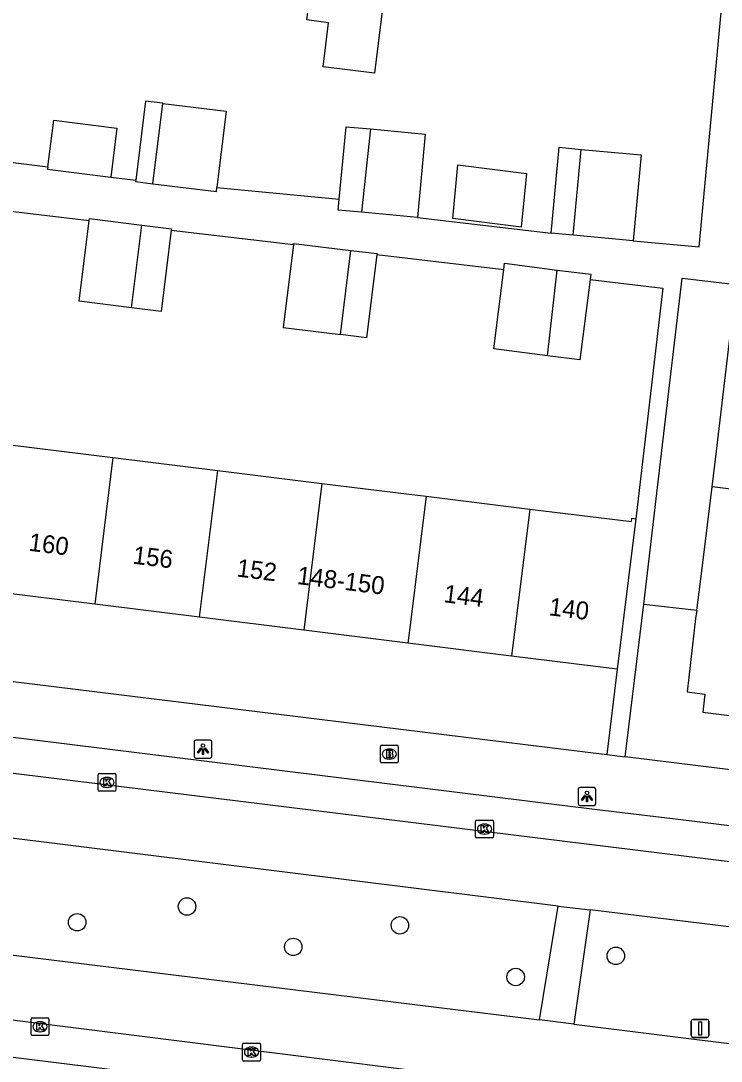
# Model space of a CAD drawing. Extents: x 158087 to 159494, y 382905 to 383981.
# Drawn here: x 158478.3 to 158517.5, y 383380.9 to 383439.1 of the extents above; entities that cross this region are included whole.
import ezdxf

# ---------------------------------------------------------------- set-up
doc = ezdxf.new("R2010")
doc.units = 0
for name, color, linetype in [('IMGEO_Boom', 7, 'Continuous'), ('IMGEO_Brandkraan', 7, 'Continuous'), ('IMGEO_Kolk', 7, 'Continuous'), ('IMGEO_Lichtpunt', 7, 'Continuous'), ('IMGEO_Pand', 7, 'Continuous'), ('IMGEO_Pand_nummerreeks', 7, 'Continuous'), ('IMGEO_Rijbaan_lokaal_gesloten', 7, 'Continuous'), ('IMGEO_Verkeersbordpaal', 7, 'Continuous'), ('IMGEO_Voetpad_open', 7, 'Continuous')]:
    doc.layers.add(name, color=color, linetype=linetype)

msp = doc.modelspace()

# ---------------------------------------------------------------- linework, layer by layer
at = {"layer": 'IMGEO_Boom'}
for centre in [(158487.569, 383389.572), (158481.416, 383388.692), (158499.487, 383388.521), (158493.514, 383387.313), (158511.575, 383386.812), (158505.97, 383385.631)]:
    msp.add_circle(centre, 0.489, dxfattribs=at)
at = {"layer": 'IMGEO_Brandkraan'}
for p, q in [((158498.397, 383397.676), (158498.397, 383398.528)), ((158498.472, 383398.602), (158499.324, 383398.602)), ((158498.885, 383398.382), (158498.91, 383398.382)), ((158499.398, 383398.528), (158499.398, 383397.676)), ((158498.908, 383397.822), (158498.883, 383397.822)), ((158499.324, 383397.602), (158498.472, 383397.602))]:
    msp.add_line(p, q, dxfattribs=at)
for points in [[(158498.397, 383397.676), (158498.397, 383398.528)], [(158498.472, 383398.602), (158499.324, 383398.602)], [(158499.398, 383398.528), (158499.398, 383397.676)], [(158498.745, 383398.302), (158498.745, 383397.902), (158498.958, 383397.902)], [(158498.976, 383398.302), (158498.745, 383398.302)], [(158498.924, 383398.221), (158498.87, 383398.221), (158498.87, 383398.145)], [(158498.87, 383398.145), (158498.923, 383398.145)], [(158498.932, 383398.069), (158498.87, 383398.069), (158498.87, 383397.988)], [(158498.87, 383397.988), (158498.932, 383397.988)], [(158499.324, 383397.602), (158498.472, 383397.602)]]:
    msp.add_lwpolyline(points, dxfattribs=at)
for centre, radius, start, end in [((158498.474, 383398.526), 0.0765, 91.55205, 178.44795), ((158498.474, 383398.526), 0.0765, 91.55205, 178.44795), ((158499.322, 383398.526), 0.0765, 1.55205, 88.44795), ((158499.322, 383398.526), 0.0765, 1.55205, 88.44795), ((158498.925, 383398.183), 0.0379, 267.82845, 90.93552), ((158498.933, 383398.028), 0.0404, 269.87594, 90.50774), ((158498.964, 383398.153), 0.251, 268.66757, 293.53466), ((158498.98, 383398.157), 0.145, 59.4692, 91.53667), ((158499.005, 383398.204), 0.0922, 285.51372, 58.15012), ((158499.01, 383398.012), 0.105, 301.31148, 78.98903), ((158498.474, 383397.678), 0.0765, 181.55205, 268.44795), ((158498.474, 383397.678), 0.0765, 181.55205, 268.44795), ((158499.322, 383397.678), 0.0765, 271.55205, 358.44795), ((158499.322, 383397.678), 0.0765, 271.55205, 358.44795)]:
    msp.add_arc(centre, radius, start, end, dxfattribs=at)
for centre, major_axis, ratio, start_param, end_param in [((158498.884, 383398.102), (-0.387, 0.002), 0.722429, 4.712389, 7.853982), ((158498.909, 383398.102), (-0.39, 0.002), 0.717154, 1.570796, 4.712389)]:
    msp.add_ellipse(centre, major_axis=major_axis, ratio=ratio, start_param=start_param, end_param=end_param, dxfattribs=at)
at = {"layer": 'IMGEO_Kolk'}
for p, q in [((158482.586, 383396.091), (158482.586, 383396.943)), ((158482.661, 383397.017), (158483.513, 383397.017)), ((158483.074, 383396.797), (158483.099, 383396.797)), ((158483.587, 383396.943), (158483.587, 383396.091)), ((158483.513, 383396.017), (158482.661, 383396.017)), ((158483.097, 383396.237), (158483.072, 383396.237)), ((158503.724, 383393.481), (158503.724, 383394.333)), ((158503.799, 383394.407), (158504.651, 383394.407)), ((158504.725, 383394.333), (158504.725, 383393.481)), ((158504.212, 383394.187), (158504.237, 383394.187)), ((158504.651, 383393.407), (158503.799, 383393.407)), ((158504.235, 383393.627), (158504.21, 383393.627)), ((158478.835, 383382.423), (158478.835, 383383.275)), ((158478.91, 383383.349), (158479.762, 383383.349)), ((158479.836, 383383.275), (158479.836, 383382.423)), ((158479.323, 383383.129), (158479.348, 383383.129)), ((158479.762, 383382.349), (158478.91, 383382.349)), ((158479.346, 383382.569), (158479.321, 383382.569)), ((158490.677, 383381.003), (158490.677, 383381.855)), ((158490.752, 383381.929), (158491.604, 383381.929)), ((158491.165, 383381.709), (158491.19, 383381.709)), ((158491.678, 383381.855), (158491.678, 383381.003)), ((158491.604, 383380.929), (158490.752, 383380.929)), ((158491.188, 383381.149), (158491.163, 383381.149))]:
    msp.add_line(p, q, dxfattribs=at)
for points in [[(158482.586, 383396.091), (158482.586, 383396.943)], [(158482.661, 383397.017), (158483.513, 383397.017)], [(158482.907, 383396.717), (158483.03, 383396.717), (158483.03, 383396.566), (158483.16, 383396.717), (158483.324, 383396.717), (158483.178, 383396.566), (158483.331, 383396.317), (158483.179, 383396.317), (158483.094, 383396.481), (158483.03, 383396.414), (158483.03, 383396.317), (158482.907, 383396.317), (158482.907, 383396.717)], [(158483.587, 383396.943), (158483.587, 383396.091)], [(158483.513, 383396.017), (158482.661, 383396.017)], [(158503.724, 383393.481), (158503.724, 383394.333)], [(158503.799, 383394.407), (158504.651, 383394.407)], [(158504.725, 383394.333), (158504.725, 383393.481)], [(158504.045, 383394.107), (158504.168, 383394.107), (158504.168, 383393.956), (158504.298, 383394.107), (158504.462, 383394.107), (158504.316, 383393.956), (158504.469, 383393.707), (158504.317, 383393.707), (158504.232, 383393.871), (158504.168, 383393.804), (158504.168, 383393.707), (158504.045, 383393.707), (158504.045, 383394.107)], [(158504.651, 383393.407), (158503.799, 383393.407)], [(158478.835, 383382.423), (158478.835, 383383.275)], [(158478.91, 383383.349), (158479.762, 383383.349)], [(158479.836, 383383.275), (158479.836, 383382.423)], [(158479.156, 383383.049), (158479.279, 383383.049), (158479.279, 383382.898), (158479.409, 383383.049), (158479.573, 383383.049), (158479.427, 383382.898), (158479.58, 383382.649), (158479.428, 383382.649), (158479.343, 383382.813), (158479.279, 383382.746), (158479.279, 383382.649), (158479.156, 383382.649), (158479.156, 383383.049)], [(158479.762, 383382.349), (158478.91, 383382.349)], [(158490.677, 383381.003), (158490.677, 383381.855)], [(158490.752, 383381.929), (158491.604, 383381.929)], [(158490.998, 383381.629), (158491.121, 383381.629), (158491.121, 383381.478), (158491.251, 383381.629), (158491.415, 383381.629), (158491.269, 383381.478), (158491.422, 383381.229), (158491.27, 383381.229), (158491.185, 383381.393), (158491.121, 383381.326), (158491.121, 383381.229), (158490.998, 383381.229), (158490.998, 383381.629)], [(158491.678, 383381.855), (158491.678, 383381.003)], [(158491.604, 383380.929), (158490.752, 383380.929)]]:
    msp.add_lwpolyline(points, dxfattribs=at)
for centre, start, end in [((158482.663, 383396.941), 91.55205, 178.44795), ((158482.663, 383396.941), 91.55205, 178.44795), ((158483.511, 383396.941), 1.55205, 88.44795), ((158483.511, 383396.941), 1.55205, 88.44795), ((158482.663, 383396.093), 181.55205, 268.44795), ((158482.663, 383396.093), 181.55205, 268.44795), ((158483.511, 383396.093), 271.55205, 358.44795), ((158483.511, 383396.093), 271.55205, 358.44795), ((158503.801, 383394.331), 91.55205, 178.44795), ((158503.801, 383394.331), 91.55205, 178.44795), ((158504.649, 383394.331), 1.55205, 88.44795), ((158504.649, 383394.331), 1.55205, 88.44795), ((158503.801, 383393.483), 181.55205, 268.44795), ((158503.801, 383393.483), 181.55205, 268.44795), ((158504.649, 383393.483), 271.55205, 358.44795), ((158504.649, 383393.483), 271.55205, 358.44795), ((158478.912, 383383.273), 91.55205, 178.44795), ((158478.912, 383383.273), 91.55205, 178.44795), ((158479.76, 383383.273), 1.55205, 88.44795), ((158479.76, 383383.273), 1.55205, 88.44795), ((158478.912, 383382.425), 181.55205, 268.44795), ((158478.912, 383382.425), 181.55205, 268.44795), ((158479.76, 383382.425), 271.55205, 358.44795), ((158479.76, 383382.425), 271.55205, 358.44795), ((158490.754, 383381.853), 91.55205, 178.44795), ((158490.754, 383381.853), 91.55205, 178.44795), ((158491.602, 383381.853), 1.55205, 88.44795), ((158491.602, 383381.853), 1.55205, 88.44795), ((158490.754, 383381.005), 181.55205, 268.44795), ((158490.754, 383381.005), 181.55205, 268.44795), ((158491.602, 383381.005), 271.55205, 358.44795), ((158491.602, 383381.005), 271.55205, 358.44795)]:
    msp.add_arc(centre, 0.0765, start, end, dxfattribs=at)
for centre, major_axis, ratio, start_param, end_param in [((158483.073, 383396.517), (-0.387, 0.002), 0.722429, 4.712389, 7.853982), ((158483.098, 383396.517), (-0.39, 0.002), 0.717154, 1.570796, 4.712389), ((158504.211, 383393.907), (-0.387, 0.002), 0.722429, 4.712389, 7.853982), ((158504.236, 383393.907), (-0.39, 0.002), 0.717154, 1.570796, 4.712389), ((158479.322, 383382.849), (-0.387, 0.002), 0.722429, 4.712389, 7.853982), ((158479.347, 383382.849), (-0.39, 0.002), 0.717154, 1.570796, 4.712389), ((158491.164, 383381.429), (-0.387, 0.002), 0.722429, 4.712389, 7.853982), ((158491.189, 383381.429), (-0.39, 0.002), 0.717154, 1.570796, 4.712389)]:
    msp.add_ellipse(centre, major_axis=major_axis, ratio=ratio, start_param=start_param, end_param=end_param, dxfattribs=at)
at = {"layer": 'IMGEO_Lichtpunt'}
for p, q in [((158487.963, 383398.781), (158487.963, 383397.974)), ((158487.963, 383398.781), (158487.963, 383397.974)), ((158488.865, 383398.876), (158488.057, 383398.876)), ((158488.865, 383398.876), (158488.057, 383398.876)), ((158488.959, 383397.974), (158488.959, 383398.781)), ((158488.959, 383397.974), (158488.959, 383398.781)), ((158488.057, 383397.88), (158488.865, 383397.88)), ((158488.057, 383397.88), (158488.865, 383397.88)), ((158509.46, 383396.131), (158509.46, 383395.324)), ((158509.46, 383396.131), (158509.46, 383395.324)), ((158510.362, 383396.226), (158509.554, 383396.226)), ((158510.362, 383396.226), (158509.554, 383396.226)), ((158510.456, 383395.324), (158510.456, 383396.131)), ((158510.456, 383395.324), (158510.456, 383396.131)), ((158509.554, 383395.23), (158510.362, 383395.23)), ((158509.554, 383395.23), (158510.362, 383395.23))]:
    msp.add_line(p, q, dxfattribs=at)
for points in [[(158488.337, 383398.445), (158488.376, 383398.417), (158488.188, 383398.155), (158488.15, 383398.182), (158488.337, 383398.445)], [(158488.439, 383398.397), (158488.486, 383398.397), (158488.486, 383398.075), (158488.439, 383398.075), (158488.439, 383398.397)], [(158488.549, 383398.417), (158488.587, 383398.444), (158488.774, 383398.182), (158488.735, 383398.154), (158488.549, 383398.417)], [(158509.834, 383395.795), (158509.873, 383395.767), (158509.685, 383395.505), (158509.647, 383395.532), (158509.834, 383395.795)], [(158509.936, 383395.747), (158509.983, 383395.747), (158509.983, 383395.425), (158509.936, 383395.425), (158509.936, 383395.747)], [(158510.046, 383395.767), (158510.084, 383395.794), (158510.271, 383395.532), (158510.232, 383395.504), (158510.046, 383395.767)]]:
    msp.add_lwpolyline(points, dxfattribs=at)
for centre in [(158488.462, 383398.579), (158509.959, 383395.929)]:
    msp.add_circle(centre, 0.0994, dxfattribs=at)
for centre, start, end in [((158488.057, 383398.781), 90, 180), ((158488.057, 383398.781), 90, 180), ((158488.865, 383398.781), 0, 90), ((158488.865, 383398.781), 0, 90), ((158488.057, 383397.974), 180, 270), ((158488.057, 383397.974), 180, 270), ((158488.865, 383397.974), 270, 0), ((158488.865, 383397.974), 270, 360), ((158509.554, 383396.131), 90, 180), ((158509.554, 383396.131), 90, 180), ((158510.362, 383396.131), 0, 90), ((158510.362, 383396.131), 0, 90), ((158509.554, 383395.324), 180, 270), ((158509.554, 383395.324), 180, 270), ((158510.362, 383395.324), 270, 0), ((158510.362, 383395.324), 270, 360)]:
    msp.add_arc(centre, 0.0946, start, end, dxfattribs=at)
at = {"layer": 'IMGEO_Pand'}
for points in [[(158499.119, 383444.667), (158498.064, 383436.195), (158495.188, 383436.554), (158495.495, 383439.018), (158494.273, 383439.17), (158494.738, 383442.903), (158496.734, 383442.655), (158497.017, 383444.928), (158493.033, 383445.425)], [(158486.219, 383434.5), (158486.22, 383434.509), (158485.248, 383434.63), (158484.696, 383430.206)], [(158485.659, 383430.01), (158486.219, 383434.5)], [(158486.219, 383434.5), (158489.768, 383434.063), (158489.243, 383429.791)], [(158479.78, 383430.955), (158480.105, 383433.56), (158483.634, 383433.12), (158483.293, 383430.381)], [(158496.092, 383429.148), (158496.472, 383433.2), (158497.843, 383433.072)], [(158497.843, 383433.072), (158497.33, 383428.41)], [(158497.843, 383433.072), (158500.908, 383432.785), (158500.47, 383428.115)], [(158507.961, 383427.25), (158508.402, 383432.047), (158509.644, 383431.93)], [(158509.194, 383427.123), (158509.644, 383431.93)], [(158509.644, 383431.93), (158512.993, 383431.617), (158512.543, 383426.809)], [(158479.78, 383430.955), (158479.763, 383430.821), (158483.293, 383430.381)], [(158506.567, 383430.582), (158506.286, 383427.587), (158502.45, 383428.067), (158502.731, 383431.062), (158506.567, 383430.582)], [(158484.696, 383430.206), (158484.687, 383430.131), (158485.659, 383430.01)], [(158485.659, 383430.01), (158489.215, 383429.566), (158489.243, 383429.791)], [(158497.33, 383428.41), (158496.034, 383428.531), (158496.092, 383429.148)], [(158482.093, 383427.95), (158482.107, 383428.06), (158485.029, 383427.699)], [(158500.47, 383428.115), (158497.33, 383428.41)], [(158484.456, 383423.074), (158481.537, 383423.434), (158482.093, 383427.95)], [(158484.456, 383423.074), (158485.029, 383427.699)], [(158485.029, 383427.699), (158486.696, 383427.494), (158486.686, 383427.409)], [(158486.686, 383427.409), (158486.126, 383422.869), (158484.456, 383423.074)], [(158509.194, 383427.123), (158507.961, 383427.25)], [(158512.543, 383426.809), (158509.194, 383427.123)], [(158493.524, 383426.605), (158492.953, 383421.97), (158496.156, 383421.575)], [(158493.524, 383426.605), (158493.532, 383426.672), (158496.738, 383426.277)], [(158496.156, 383421.575), (158496.738, 383426.277)], [(158496.738, 383426.277), (158498.205, 383426.097), (158498.2, 383426.056)], [(158498.2, 383426.056), (158497.626, 383421.394), (158496.156, 383421.575)], [(158507.747, 383420.389), (158504.745, 383420.77), (158505.309, 383425.219)], [(158505.309, 383425.219), (158505.352, 383425.555), (158508.299, 383425.181)], [(158507.747, 383420.389), (158508.299, 383425.181)], [(158508.299, 383425.181), (158510.172, 383424.943), (158510.135, 383424.652)], [(158510.135, 383424.652), (158509.564, 383420.158), (158507.747, 383420.389)], [(158513.15, 383406.496), (158514.197, 383415.395), (158515.295, 383424.731), (158518.309, 383424.377)], [(158516.977, 383413.047), (158517.212, 383415.041), (158518.309, 383424.377)], [(158477.672, 383415.395), (158483.417, 383414.687)], [(158483.417, 383414.687), (158482.4, 383406.479)], [(158483.417, 383414.687), (158489.286, 383413.963)], [(158488.269, 383405.752), (158489.286, 383413.963)], [(158489.286, 383413.963), (158495.123, 383413.243)], [(158495.123, 383413.243), (158494.105, 383405.029)], [(158495.123, 383413.243), (158500, 383412.641), (158500.95, 383412.524)], [(158516.105, 383406.144), (158516.046, 383405.683), (158515.564, 383401.587), (158516.567, 383401.455), (158516.457, 383400.452), (158521.373, 383399.839), (158521.495, 383400.82), (158522.515, 383400.689), (158523.459, 383408.304), (158523.94, 383412.184), (158516.977, 383413.047)], [(158516.105, 383406.144), (158516.31, 383407.741), (158516.977, 383413.047)], [(158500.95, 383412.524), (158500, 383404.857), (158499.932, 383404.306)], [(158500.95, 383412.524), (158506.758, 383411.807)], [(158506.758, 383411.807), (158505.74, 383403.586)], [(158506.758, 383411.807), (158512.458, 383411.104), (158512.482, 383411.297), (158512.7, 383411.269)], [(158512.7, 383411.269), (158512.272, 383407.816), (158511.657, 383402.853)], [(158482.4, 383406.479), (158476.656, 383407.191)], [(158488.269, 383405.752), (158482.4, 383406.479)], [(158513.15, 383406.496), (158516.105, 383406.144)], [(158494.105, 383405.029), (158488.269, 383405.752)], [(158499.932, 383404.306), (158494.105, 383405.029)], [(158505.74, 383403.586), (158499.932, 383404.306)], [(158511.657, 383402.853), (158505.74, 383403.586)]]:
    msp.add_lwpolyline(points, dxfattribs=at)
at = {"layer": 'IMGEO_Rijbaan_lokaal_gesloten'}
for points in [[(158580.062, 383384.432), (158538.992, 383389.488), (158465.723, 383398.507)], [(158508.34, 383389.597), (158465.277, 383394.941)], [(158508.34, 383389.597), (158510.146, 383389.39)], [(158579.65, 383380.875), (158538.64, 383385.899), (158510.146, 383389.39)], [(158463.867, 383388.573), (158507.312, 383383.231)], [(158507.896, 383379.433), (158463.372, 383385.022)], [(158509.228, 383382.991), (158507.312, 383383.231)], [(158509.228, 383382.991), (158538.003, 383379.406), (158577.958, 383374.428)]]:
    msp.add_lwpolyline(points, dxfattribs=at)
at = {"layer": 'IMGEO_Verkeersbordpaal'}
for p, q in [((158515.897, 383383.254), (158516.687, 383383.254)), ((158516.687, 383383.254), (158515.897, 383383.254)), ((158515.797, 383382.354), (158515.797, 383383.154)), ((158515.797, 383383.154), (158515.797, 383382.354)), ((158516.787, 383383.154), (158516.787, 383382.354)), ((158516.787, 383382.354), (158516.787, 383383.154)), ((158516.687, 383382.254), (158515.897, 383382.254)), ((158515.897, 383382.254), (158516.687, 383382.254))]:
    msp.add_line(p, q, dxfattribs=at)
msp.add_lwpolyline([(158516.217, 383383.129), (158516.367, 383383.129), (158516.367, 383382.379), (158516.217, 383382.379), (158516.217, 383383.129)], dxfattribs=at)
for centre, start, end in [((158515.897, 383383.154), 90, 180), ((158515.897, 383383.154), 90, 180), ((158516.687, 383383.154), 0, 90), ((158516.687, 383383.154), 360, 90), ((158515.897, 383382.354), 180, 270), ((158515.897, 383382.354), 180, 270), ((158516.687, 383382.354), 270, 0), ((158516.687, 383382.354), 270, 0)]:
    msp.add_arc(centre, 0.1, start, end, dxfattribs=at)
at = {"layer": 'IMGEO_Voetpad_open'}
for points in [[(158512.543, 383426.809), (158516.244, 383426.473), (158518.558, 383451.137)], [(158477.242, 383431.263), (158479.78, 383430.955)], [(158483.293, 383430.381), (158484.696, 383430.206)], [(158489.243, 383429.791), (158496.092, 383429.148)], [(158474.703, 383428.819), (158482.093, 383427.95)], [(158500.47, 383428.115), (158507.961, 383427.25)], [(158486.686, 383427.409), (158493.524, 383426.605)], [(158498.2, 383426.056), (158505.309, 383425.219)], [(158510.135, 383424.652), (158514.217, 383424.172), (158512.7, 383411.269)], [(158512.098, 383397.946), (158513.15, 383406.496)], [(158459.442, 383404.425), (158511.069, 383398.073)], [(158511.657, 383402.853), (158511.069, 383398.073)], [(158469.214, 383400.114), (158510.534, 383395.003), (158515.06, 383394.465), (158539.189, 383391.495), (158577.108, 383386.827)], [(158511.069, 383398.073), (158512.098, 383397.946)], [(158587.052, 383388.722), (158539.491, 383394.575), (158512.098, 383397.946)], [(158507.312, 383383.231), (158508.34, 383389.597)], [(158510.146, 383389.39), (158509.228, 383382.991)], [(158504.059, 383377.884), (158466.503, 383382.527)]]:
    msp.add_lwpolyline(points, dxfattribs=at)

# ---------------------------------------------------------------- texts
at = {"layer": 'IMGEO_Pand_nummerreeks'}
for s, rotation, p in [('160', 352.92783, (158478.663, 383409.482)), ('156', 352.92908, (158484.494, 383408.759)), ('152', 352.93027, (158490.311, 383408.039)), ('148-150', 352.92703, (158493.693, 383407.619)), ('144', 352.93367, (158501.902, 383406.601)), ('140', 352.93094, (158507.794, 383405.871))]:
    msp.add_text(s, height=1, rotation=rotation, dxfattribs=at).set_placement(p)

doc.saveas('drawing.dxf')
